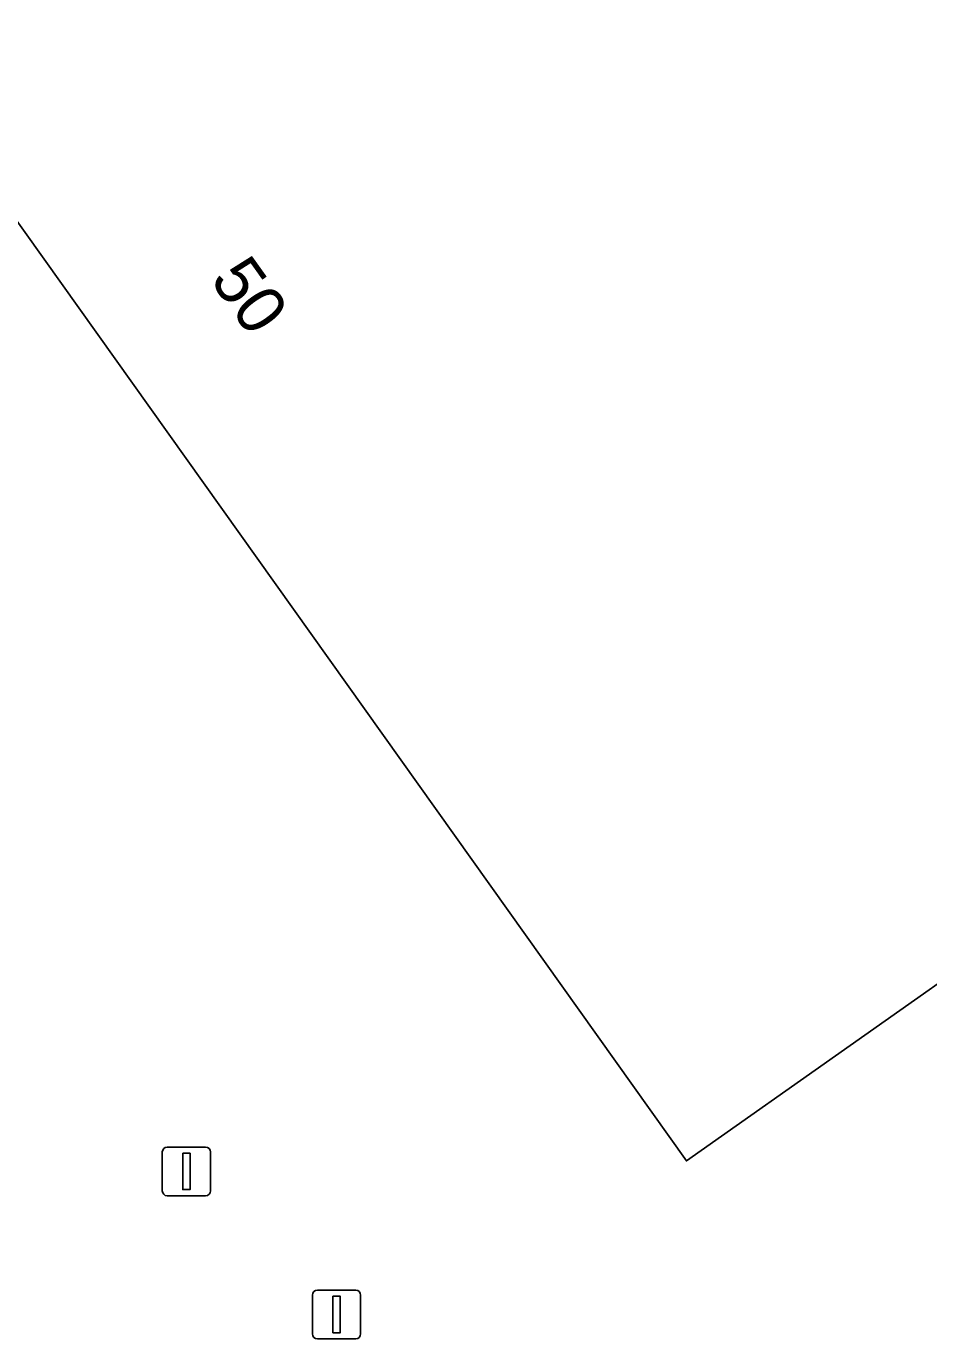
# Model space of a CAD drawing. Extents: x 163043 to 165076, y 382019 to 382874.
# Drawn here: x 164658.19 to 164676.75, y 382534.79 to 382561.77 of the extents above; entities that cross this region are included whole.
import ezdxf

# ---------------------------------------------------------------- set-up
doc = ezdxf.new("R2010")
doc.units = 0
for name, color, linetype in [('IMGEO_Afsluitpaal', 7, 'Continuous'), ('IMGEO_Groenvoorziening', 7, 'Continuous'), ('IMGEO_Pand', 7, 'Continuous'), ('IMGEO_Pand_nummerreeks', 7, 'Continuous')]:
    doc.layers.add(name, color=color, linetype=linetype)

msp = doc.modelspace()

# ---------------------------------------------------------------- linework, layer by layer
at = {"layer": 'IMGEO_Afsluitpaal'}
for p, q in [((164660.989, 382537.828), (164660.989, 382538.628)), ((164660.989, 382538.628), (164660.989, 382537.828)), ((164661.089, 382538.728), (164661.879, 382538.728)), ((164661.879, 382538.728), (164661.089, 382538.728)), ((164661.979, 382538.628), (164661.979, 382537.828)), ((164661.979, 382537.828), (164661.979, 382538.628)), ((164661.879, 382537.728), (164661.089, 382537.728)), ((164661.089, 382537.728), (164661.879, 382537.728)), ((164664.077, 382534.887), (164664.077, 382535.687)), ((164664.077, 382535.687), (164664.077, 382534.887)), ((164664.177, 382535.787), (164664.967, 382535.787)), ((164664.967, 382535.787), (164664.177, 382535.787)), ((164665.067, 382535.687), (164665.067, 382534.887)), ((164665.067, 382534.887), (164665.067, 382535.687)), ((164664.967, 382534.787), (164664.177, 382534.787)), ((164664.177, 382534.787), (164664.967, 382534.787))]:
    msp.add_line(p, q, dxfattribs=at)
for points in [[(164661.409, 382538.603), (164661.559, 382538.603), (164661.559, 382537.853), (164661.409, 382537.853), (164661.409, 382538.603)], [(164664.497, 382535.662), (164664.647, 382535.662), (164664.647, 382534.912), (164664.497, 382534.912), (164664.497, 382535.662)]]:
    msp.add_lwpolyline(points, dxfattribs=at)
for centre, start, end in [((164661.089, 382538.628), 90, 180), ((164661.089, 382538.628), 90, 180), ((164661.879, 382538.628), 0, 90), ((164661.879, 382538.628), 360, 90), ((164661.089, 382537.828), 180, 270), ((164661.089, 382537.828), 180, 270), ((164661.879, 382537.828), 270, 0), ((164661.879, 382537.828), 270, 0), ((164664.177, 382535.687), 90, 180), ((164664.177, 382535.687), 90, 180), ((164664.967, 382535.687), 0, 90), ((164664.967, 382535.687), 360, 90), ((164664.177, 382534.887), 180, 270), ((164664.177, 382534.887), 180, 270), ((164664.967, 382534.887), 270, 0), ((164664.967, 382534.887), 270, 0)]:
    msp.add_arc(centre, 0.1, start, end, dxfattribs=at)
at = {"layer": 'IMGEO_Groenvoorziening'}
msp.add_lwpolyline([(164680.988, 382539.657), (164678.495, 382543.191), (164671.763, 382538.445), (164648.982, 382570.43), (164646.503, 382568.756), (164633.566, 382560.023), (164634.992, 382557.476)], dxfattribs=at)
at = {"layer": 'IMGEO_Pand'}
msp.add_lwpolyline([(164674.103, 382588.253), (164649.682, 382570.927), (164648.982, 382570.43), (164671.763, 382538.445), (164678.495, 382543.191), (164680.988, 382539.657), (164681.403, 382539.068), (164699.715, 382552.158), (164699.281, 382552.769)], close=True, dxfattribs=at)

# ---------------------------------------------------------------- texts
at = {"layer": 'IMGEO_Pand_nummerreeks'}
msp.add_text('50', height=1, rotation=305.4606, dxfattribs=at).set_placement((164661.953, 382556.562))

doc.saveas('drawing.dxf')
